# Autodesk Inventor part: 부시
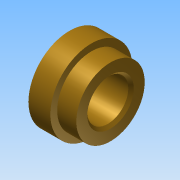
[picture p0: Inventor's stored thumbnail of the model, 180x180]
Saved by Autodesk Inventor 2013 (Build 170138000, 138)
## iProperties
Company: 한국ATC센터
Created: 2014-08
Part Number: 부시
Document SubType Name: Modeling
Designer: KYOUNG IL JANG
Density: 7.86 g/cm^3
Checked By: KYOUNG IL JANG
Material: 강철, 연강
Mass: 50.2336 g
Surface Area: 30.183 cm^2
Volume: 6.39105 cm^3
Author: KYOUNG IL JANG
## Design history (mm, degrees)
sketch "스케치1"
  geometry: L1 (0, 0)-(15, 0); L2 (0, 7.5)-(15, 7.5); L3 (15, 7.5)-(15, 12.5); L4 (15, 12.5)-(8, 12.5); L5 (8, 12.5)-(8, 15); L6 (8, 15)-(0, 15); L7 (0, 15)-(0, 7.5)
  constraints: 14 end point, 4 parallel, 2 vertical alignment, 1 horizontal, 1 perpendicular, 1 vertical
  dimensions: "d0" = 15 distance of L1.start L1.end; "d1" = 15 diameter of L2 L1; "d2" = 25 diameter of L4 L1; "d3" = 8 distance of L5.end L6.end; "d4" = 30 diameter of L6 L1
revolve "회전1" sketch "스케치1" stored, may be unused: angle "d5" = 90 deg
chamfer "모따기1" distance "d6" = 1; stored, may be unused: second distance "d7" = 2, angle "d8" = 45 deg
node "솔리드1"
